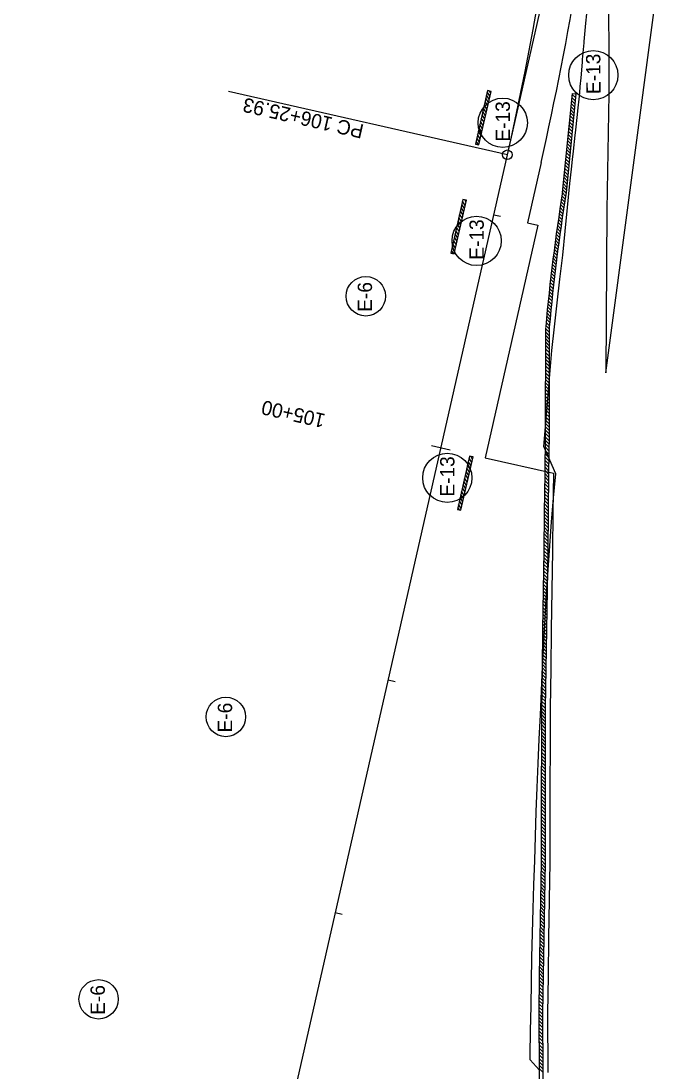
# Model space of a CAD drawing. Extents: x 1710760 to 1713003, y 548603 to 551142.
# Drawn here: x 1712246.8 to 1712516.1, y 550141.7 to 550581.9 of the extents above; entities that cross this region are included whole.
import ezdxf

# ---------------------------------------------------------------- set-up
doc = ezdxf.new("R2010")
doc.units = 0
for name, color, linetype in [('R_Erosion', 7, 'Continuous'), ('R_Erosion_STG 2', 7, 'Continuous'), ('R_Horz Alg', 7, 'Continuous'), ('R_Horz Alg Annot', 7, 'Continuous'), ('R_MOT', 7, 'Continuous'), ('R_No Plot', 7, 'Continuous'), ('R_Proposed Const Limits_Fill', 7, 'Continuous')]:
    doc.layers.add(name, color=color, linetype=linetype)

msp = doc.modelspace()

# ---------------------------------------------------------------- linework, layer by layer
at = {"layer": 'R_Erosion'}
for p, q in [((1712438.87, 550529.97), (1712443.96, 550552.4)), ((1712443.2, 550549.06), (1712442.07, 550550.86)), ((1712443.52, 550550.44), (1712442.39, 550552.23)), ((1712443.83, 550551.82), (1712443.38, 550552.53)), ((1712473.95, 550510.04), (1712478.07, 550551.54)), ((1712479.56, 550551.39), (1712475.44, 550509.9)), ((1712479.4, 550549.75), (1712478.03, 550551.14)), ((1712478.07, 550551.54), (1712479.56, 550551.39)), ((1712479.52, 550551.05), (1712479.14, 550551.43)), ((1712442.26, 550544.92), (1712441.13, 550546.72)), ((1712442.58, 550546.3), (1712441.45, 550548.1)), ((1712442.89, 550547.68), (1712441.76, 550549.48)), ((1712479.01, 550545.88), (1712477.64, 550547.26)), ((1712479.14, 550547.17), (1712477.77, 550548.55)), ((1712479.27, 550548.46), (1712477.9, 550549.85)), ((1712441.32, 550540.79), (1712440.19, 550542.58)), ((1712441.64, 550542.17), (1712440.51, 550543.96)), ((1712441.95, 550543.54), (1712440.82, 550545.34)), ((1712478.5, 550540.71), (1712477.13, 550542.09)), ((1712478.63, 550542), (1712477.26, 550543.38)), ((1712478.75, 550543.29), (1712477.38, 550544.68)), ((1712478.88, 550544.58), (1712477.51, 550545.97)), ((1712440.39, 550536.65), (1712439.25, 550538.44)), ((1712440.7, 550538.03), (1712439.57, 550539.82)), ((1712441.01, 550539.41), (1712439.88, 550541.2)), ((1712478.11, 550536.83), (1712476.74, 550538.21)), ((1712478.24, 550538.12), (1712476.87, 550539.51)), ((1712478.37, 550539.41), (1712477, 550540.8)), ((1712439.13, 550531.13), (1712438, 550532.93)), ((1712439.45, 550532.51), (1712438.32, 550534.31)), ((1712439.76, 550533.89), (1712438.63, 550535.69)), ((1712440.07, 550535.27), (1712438.94, 550537.06)), ((1712477.6, 550531.66), (1712476.23, 550533.04)), ((1712477.73, 550532.95), (1712476.36, 550534.34)), ((1712477.86, 550534.24), (1712476.49, 550535.63)), ((1712477.99, 550535.54), (1712476.62, 550536.92)), ((1712438.65, 550530.02), (1712437.69, 550531.55)), ((1712477.22, 550527.78), (1712475.85, 550529.17)), ((1712477.35, 550529.07), (1712475.98, 550530.46)), ((1712477.47, 550530.37), (1712476.1, 550531.75)), ((1712476.83, 550523.9), (1712475.46, 550525.29)), ((1712476.96, 550525.2), (1712475.59, 550526.58)), ((1712477.09, 550526.49), (1712475.72, 550527.87)), ((1712476.32, 550518.73), (1712474.95, 550520.12)), ((1712476.45, 550520.03), (1712475.08, 550521.41)), ((1712476.58, 550521.32), (1712475.21, 550522.7)), ((1712476.7, 550522.61), (1712475.33, 550524)), ((1712475.94, 550514.86), (1712474.57, 550516.24)), ((1712476.06, 550516.15), (1712474.69, 550517.53)), ((1712476.19, 550517.44), (1712474.82, 550518.83)), ((1712475.41, 550509.7), (1712474.05, 550511.07)), ((1712475.55, 550510.98), (1712474.18, 550512.36)), ((1712475.68, 550512.27), (1712474.31, 550513.66)), ((1712475.81, 550513.56), (1712474.44, 550514.95)), ((1712428.56, 550484.29), (1712433.65, 550506.72)), ((1712433.49, 550505.99), (1712432.92, 550506.89)), ((1712474.82, 550506.03), (1712473.51, 550507.35)), ((1712475.02, 550507.25), (1712473.71, 550508.58)), ((1712475.21, 550508.48), (1712473.91, 550509.8)), ((1712432.23, 550500.47), (1712431.1, 550502.27)), ((1712432.55, 550501.85), (1712431.42, 550503.65)), ((1712432.86, 550503.23), (1712431.73, 550505.03)), ((1712433.17, 550504.61), (1712432.04, 550506.4)), ((1712474.07, 550501.1), (1712472.75, 550502.43)), ((1712474.25, 550502.34), (1712472.94, 550503.67)), ((1712474.44, 550503.57), (1712473.13, 550504.9)), ((1712474.63, 550504.8), (1712473.32, 550506.12)), ((1712431.29, 550496.33), (1712430.16, 550498.13)), ((1712431.61, 550497.71), (1712430.48, 550499.51)), ((1712431.92, 550499.09), (1712430.79, 550500.89)), ((1712473.52, 550497.39), (1712472.2, 550498.73)), ((1712473.7, 550498.63), (1712472.38, 550499.96)), ((1712473.88, 550499.87), (1712472.56, 550501.2)), ((1712430.35, 550492.2), (1712429.22, 550493.99)), ((1712430.67, 550493.58), (1712429.54, 550495.37)), ((1712430.98, 550494.96), (1712429.85, 550496.75)), ((1712472.81, 550492.42), (1712471.48, 550493.76)), ((1712472.98, 550493.66), (1712471.66, 550495)), ((1712473.16, 550494.91), (1712471.84, 550496.25)), ((1712473.34, 550496.15), (1712472.02, 550497.49)), ((1712429.41, 550488.06), (1712428.28, 550489.86)), ((1712429.73, 550489.44), (1712428.6, 550491.23)), ((1712430.04, 550490.82), (1712428.91, 550492.61)), ((1712472.3, 550488.67), (1712470.97, 550490.02)), ((1712472.47, 550489.92), (1712471.14, 550491.27)), ((1712472.64, 550491.17), (1712471.31, 550492.51)), ((1712428.19, 550484.37), (1712427.34, 550485.72)), ((1712428.79, 550485.3), (1712427.66, 550487.1)), ((1712429.1, 550486.68), (1712427.97, 550488.48)), ((1712471.64, 550483.64), (1712470.3, 550485)), ((1712471.8, 550484.9), (1712470.47, 550486.26)), ((1712471.97, 550486.16), (1712470.63, 550487.51)), ((1712472.13, 550487.42), (1712470.8, 550488.76)), ((1712471.17, 550479.86), (1712469.83, 550481.21)), ((1712471.33, 550481.12), (1712469.98, 550482.48)), ((1712471.48, 550482.38), (1712470.14, 550483.74)), ((1712470.57, 550474.78), (1712469.21, 550476.14)), ((1712470.71, 550476.05), (1712469.36, 550477.41)), ((1712470.86, 550477.32), (1712469.52, 550478.68)), ((1712471.02, 550478.59), (1712469.67, 550479.95)), ((1712470.13, 550470.95), (1712468.78, 550472.32)), ((1712470.27, 550472.23), (1712468.92, 550473.6)), ((1712470.42, 550473.5), (1712469.07, 550474.87)), ((1712469.58, 550465.82), (1712468.22, 550467.2)), ((1712469.72, 550467.1), (1712468.35, 550468.48)), ((1712469.85, 550468.39), (1712468.49, 550469.76)), ((1712469.99, 550469.67), (1712468.63, 550471.04)), ((1712469.19, 550461.95), (1712467.82, 550463.33)), ((1712469.32, 550463.24), (1712467.95, 550464.62)), ((1712469.45, 550464.53), (1712468.08, 550465.91)), ((1712468.69, 550456.76), (1712467.32, 550458.15)), ((1712468.81, 550458.06), (1712467.44, 550459.45)), ((1712468.94, 550459.36), (1712467.56, 550460.75)), ((1712469.06, 550460.65), (1712467.69, 550462.04)), ((1712468.39, 550452.8), (1712466.96, 550454.25)), ((1712468.46, 550454.16), (1712467.08, 550455.55)), ((1712468.58, 550455.46), (1712467.2, 550456.85)), ((1712468.39, 550451.38), (1712466.89, 550452.89)), ((1712468.39, 550449.96), (1712466.89, 550451.47)), ((1712468.38, 550448.54), (1712466.89, 550450.06)), ((1712468.38, 550447.12), (1712466.88, 550448.64)), ((1712468.38, 550445.7), (1712466.88, 550447.22)), ((1712468.38, 550444.28), (1712466.88, 550445.8)), ((1712468.37, 550441.45), (1712466.87, 550442.96)), ((1712468.37, 550440.03), (1712466.87, 550441.54)), ((1712468.37, 550442.87), (1712466.88, 550444.38)), ((1712468.36, 550437.19), (1712466.86, 550438.7)), ((1712468.36, 550435.77), (1712466.86, 550437.28)), ((1712468.36, 550438.61), (1712466.87, 550440.12)), ((1712468.35, 550432.93), (1712466.85, 550434.45)), ((1712468.35, 550431.51), (1712466.85, 550433.03)), ((1712468.35, 550434.35), (1712466.86, 550435.86)), ((1712468.34, 550427.26), (1712466.84, 550428.77)), ((1712468.34, 550425.84), (1712466.84, 550427.35)), ((1712468.35, 550430.09), (1712466.85, 550431.61)), ((1712468.34, 550428.67), (1712466.85, 550430.19)), ((1712468.33, 550423), (1712466.83, 550424.51)), ((1712468.33, 550421.58), (1712466.83, 550423.09)), ((1712468.33, 550424.42), (1712466.84, 550425.93)), ((1712468.32, 550418.74), (1712466.82, 550420.25)), ((1712468.32, 550417.32), (1712466.82, 550418.84)), ((1712468.32, 550420.16), (1712466.83, 550421.67)), ((1712468.31, 550413.06), (1712466.81, 550414.58)), ((1712468.32, 550415.9), (1712466.82, 550417.42)), ((1712468.31, 550414.48), (1712466.82, 550416)), ((1712468.3, 550408.81), (1712466.8, 550410.32)), ((1712468.31, 550411.65), (1712466.81, 550413.16)), ((1712468.3, 550410.23), (1712466.81, 550411.74)), ((1712468.26, 550404.59), (1712466.77, 550406.09)), ((1712468.27, 550405.99), (1712466.79, 550407.49)), ((1712468.29, 550407.4), (1712466.8, 550408.9)), ((1712468.21, 550400.37), (1712466.72, 550401.87)), ((1712468.22, 550401.77), (1712466.74, 550403.27)), ((1712468.24, 550403.18), (1712466.76, 550404.68)), ((1712431.32, 550376.76), (1712436.41, 550399.19)), ((1712435.56, 550395.45), (1712434.43, 550397.24)), ((1712435.87, 550396.83), (1712434.74, 550398.62)), ((1712436.19, 550398.21), (1712435.42, 550399.42)), ((1712468.16, 550396.15), (1712466.68, 550397.65)), ((1712468.18, 550397.56), (1712466.69, 550399.06)), ((1712468.19, 550398.96), (1712466.71, 550400.46)), ((1712434.62, 550391.31), (1712433.49, 550393.1)), ((1712434.93, 550392.69), (1712433.8, 550394.48)), ((1712435.25, 550394.07), (1712434.12, 550395.86)), ((1712468.11, 550391.93), (1712466.63, 550393.43)), ((1712468.13, 550393.34), (1712466.64, 550394.84)), ((1712468.14, 550394.74), (1712466.66, 550396.24)), ((1712433.68, 550387.17), (1712432.55, 550388.97)), ((1712433.99, 550388.55), (1712432.86, 550390.35)), ((1712434.31, 550389.93), (1712433.18, 550391.73)), ((1712468.05, 550386.31), (1712466.56, 550387.81)), ((1712468.06, 550387.72), (1712466.58, 550389.21)), ((1712468.08, 550389.12), (1712466.6, 550390.62)), ((1712468.1, 550390.53), (1712466.61, 550392.03)), ((1712432.43, 550381.66), (1712431.3, 550383.45)), ((1712432.74, 550383.04), (1712431.61, 550384.83)), ((1712433.05, 550384.41), (1712431.92, 550386.21)), ((1712433.37, 550385.79), (1712432.24, 550387.59)), ((1712468, 550382.09), (1712466.52, 550383.59)), ((1712468.02, 550383.5), (1712466.53, 550385)), ((1712468.03, 550384.9), (1712466.55, 550386.4)), ((1712431.49, 550377.52), (1712430.36, 550379.31)), ((1712431.8, 550378.9), (1712430.67, 550380.69)), ((1712432.11, 550380.28), (1712430.98, 550382.07)), ((1712467.95, 550377.87), (1712466.47, 550379.37)), ((1712467.97, 550379.28), (1712466.48, 550380.78)), ((1712467.98, 550380.69), (1712466.5, 550382.19)), ((1712430.69, 550376.9), (1712430.04, 550377.93)), ((1712467.9, 550373.66), (1712466.42, 550375.16)), ((1712467.92, 550375.06), (1712466.44, 550376.56)), ((1712467.94, 550376.47), (1712466.45, 550377.97)), ((1712467.86, 550369.44), (1712466.37, 550370.94)), ((1712467.87, 550370.84), (1712466.39, 550372.34)), ((1712467.89, 550372.25), (1712466.4, 550373.75)), ((1712467.81, 550365.22), (1712466.32, 550366.72)), ((1712467.82, 550366.63), (1712466.34, 550368.13)), ((1712467.84, 550368.03), (1712466.36, 550369.53)), ((1712467.76, 550361), (1712466.28, 550362.5)), ((1712467.77, 550362.41), (1712466.29, 550363.91)), ((1712467.79, 550363.81), (1712466.31, 550365.31)), ((1712467.68, 550355.4), (1712466.2, 550356.89)), ((1712467.7, 550356.8), (1712466.22, 550358.29)), ((1712467.72, 550358.2), (1712466.24, 550359.69)), ((1712467.74, 550359.6), (1712466.26, 550361.1)), ((1712467.61, 550351.2), (1712466.14, 550352.69)), ((1712467.63, 550352.6), (1712466.16, 550354.09)), ((1712467.66, 550354), (1712466.18, 550355.49)), ((1712467.55, 550347), (1712466.07, 550348.49)), ((1712467.57, 550348.4), (1712466.09, 550349.89)), ((1712467.59, 550349.8), (1712466.11, 550351.29)), ((1712467.48, 550342.79), (1712466.01, 550344.29)), ((1712467.5, 550344.19), (1712466.03, 550345.69)), ((1712467.53, 550345.6), (1712466.05, 550347.09)), ((1712467.42, 550338.59), (1712465.94, 550340.09)), ((1712467.44, 550339.99), (1712465.96, 550341.49)), ((1712467.46, 550341.39), (1712465.98, 550342.89)), ((1712467.35, 550334.39), (1712465.88, 550335.89)), ((1712467.38, 550335.79), (1712465.9, 550337.29)), ((1712467.4, 550337.19), (1712465.92, 550338.69)), ((1712467.29, 550330.19), (1712465.81, 550331.69)), ((1712467.31, 550331.59), (1712465.83, 550333.09)), ((1712467.33, 550332.99), (1712465.86, 550334.49)), ((1712467.2, 550324.59), (1712465.73, 550326.08)), ((1712467.22, 550325.99), (1712465.75, 550327.48)), ((1712467.25, 550327.39), (1712465.77, 550328.88)), ((1712467.27, 550328.79), (1712465.79, 550330.29)), ((1712467.14, 550320.39), (1712465.66, 550321.88)), ((1712467.16, 550321.79), (1712465.68, 550323.28)), ((1712467.18, 550323.19), (1712465.7, 550324.68)), ((1712467.07, 550316.19), (1712465.6, 550317.68)), ((1712467.1, 550317.59), (1712465.62, 550319.08)), ((1712467.12, 550318.99), (1712465.64, 550320.48)), ((1712467.01, 550311.99), (1712465.53, 550313.48)), ((1712467.03, 550313.39), (1712465.55, 550314.88)), ((1712467.05, 550314.79), (1712465.57, 550316.28)), ((1712466.94, 550307.79), (1712465.47, 550309.28)), ((1712466.97, 550309.19), (1712465.49, 550310.68)), ((1712466.99, 550310.59), (1712465.51, 550312.08)), ((1712466.88, 550303.59), (1712465.4, 550305.08)), ((1712466.9, 550304.99), (1712465.42, 550306.48)), ((1712466.92, 550306.39), (1712465.45, 550307.88)), ((1712466.81, 550299.39), (1712465.34, 550300.88)), ((1712466.84, 550300.79), (1712465.36, 550302.28)), ((1712466.86, 550302.19), (1712465.38, 550303.68)), ((1712466.73, 550293.78), (1712465.25, 550295.28)), ((1712466.75, 550295.18), (1712465.27, 550296.68)), ((1712466.77, 550296.58), (1712465.29, 550298.08)), ((1712466.79, 550297.98), (1712465.32, 550299.48)), ((1712466.72, 550289.53), (1712465.22, 550291.04)), ((1712466.73, 550292.36), (1712465.23, 550293.88)), ((1712466.72, 550290.94), (1712465.23, 550292.46)), ((1712466.72, 550288.11), (1712465.22, 550289.62)), ((1712466.72, 550286.69), (1712465.22, 550288.2)), ((1712466.71, 550285.27), (1712465.22, 550286.78)), ((1712466.71, 550283.85), (1712465.21, 550285.36)), ((1712466.71, 550282.43), (1712465.21, 550283.94)), ((1712466.7, 550281.01), (1712465.21, 550282.52)), ((1712466.7, 550278.17), (1712465.2, 550279.68)), ((1712466.7, 550276.75), (1712465.2, 550278.26)), ((1712466.7, 550279.59), (1712465.21, 550281.1)), ((1712466.69, 550273.91), (1712465.19, 550275.43)), ((1712466.69, 550272.49), (1712465.19, 550274.01)), ((1712466.69, 550275.33), (1712465.2, 550276.84)), ((1712466.68, 550268.23), (1712465.18, 550269.75)), ((1712466.69, 550271.07), (1712465.19, 550272.59)), ((1712466.68, 550269.65), (1712465.19, 550271.17)), ((1712466.68, 550266.81), (1712465.18, 550268.33)), ((1712466.68, 550265.4), (1712465.18, 550266.91)), ((1712466.67, 550263.98), (1712465.18, 550265.49)), ((1712466.67, 550262.56), (1712465.17, 550264.07)), ((1712466.67, 550261.14), (1712465.17, 550262.65)), ((1712466.66, 550259.72), (1712465.17, 550261.23)), ((1712466.66, 550258.3), (1712465.16, 550259.81)), ((1712466.66, 550256.88), (1712465.16, 550258.39)), ((1712466.66, 550255.46), (1712465.16, 550256.97)), ((1712466.65, 550252.62), (1712465.15, 550254.13)), ((1712466.65, 550251.2), (1712465.15, 550252.72)), ((1712466.65, 550249.78), (1712465.15, 550251.3)), ((1712466.65, 550254.04), (1712465.16, 550255.55)), ((1712466.64, 550246.94), (1712465.14, 550248.46)), ((1712466.64, 550245.52), (1712465.14, 550247.04)), ((1712466.64, 550248.36), (1712465.15, 550249.88)), ((1712466.63, 550241.27), (1712465.13, 550242.78)), ((1712466.64, 550244.1), (1712465.14, 550245.62)), ((1712466.63, 550242.69), (1712465.14, 550244.2)), ((1712466.62, 550237.01), (1712465.12, 550238.52)), ((1712466.63, 550239.85), (1712465.13, 550241.36)), ((1712466.62, 550238.43), (1712465.13, 550239.94)), ((1712466.62, 550235.59), (1712465.12, 550237.1)), ((1712466.62, 550234.17), (1712465.12, 550235.68)), ((1712466.61, 550232.75), (1712465.12, 550234.26)), ((1712466.61, 550231.33), (1712465.11, 550232.84)), ((1712466.61, 550229.91), (1712465.11, 550231.42)), ((1712466.59, 550228.5), (1712465.11, 550230)), ((1712466.53, 550224.3), (1712465.05, 550225.8)), ((1712466.55, 550225.7), (1712465.07, 550227.2)), ((1712466.57, 550227.1), (1712465.1, 550228.6)), ((1712466.46, 550220.1), (1712464.99, 550221.6)), ((1712466.48, 550221.5), (1712465.01, 550223)), ((1712466.51, 550222.9), (1712465.03, 550224.4)), ((1712466.37, 550214.5), (1712464.9, 550216)), ((1712466.4, 550215.9), (1712464.92, 550217.4)), ((1712466.42, 550217.3), (1712464.94, 550218.8)), ((1712466.44, 550218.7), (1712464.96, 550220.2)), ((1712466.31, 550210.3), (1712464.83, 550211.8)), ((1712466.33, 550211.7), (1712464.85, 550213.2)), ((1712466.35, 550213.1), (1712464.88, 550214.6)), ((1712466.24, 550206.1), (1712464.77, 550207.6)), ((1712466.27, 550207.5), (1712464.79, 550209)), ((1712466.29, 550208.9), (1712464.81, 550210.4)), ((1712466.18, 550201.9), (1712464.7, 550203.4)), ((1712466.2, 550203.3), (1712464.72, 550204.8)), ((1712466.22, 550204.7), (1712464.74, 550206.2)), ((1712466.11, 550197.7), (1712464.64, 550199.2)), ((1712466.13, 550199.1), (1712464.66, 550200.6)), ((1712466.16, 550200.5), (1712464.68, 550202)), ((1712466.05, 550193.5), (1712464.57, 550195)), ((1712466.07, 550194.9), (1712464.59, 550196.4)), ((1712466.09, 550196.3), (1712464.61, 550197.8)), ((1712465.98, 550189.3), (1712464.5, 550190.8)), ((1712466, 550190.7), (1712464.53, 550192.2)), ((1712466.02, 550192.1), (1712464.55, 550193.6)), ((1712465.89, 550183.7), (1712464.42, 550185.2)), ((1712465.91, 550185.1), (1712464.44, 550186.6)), ((1712465.94, 550186.5), (1712464.46, 550188)), ((1712465.96, 550187.9), (1712464.48, 550189.4)), ((1712465.83, 550179.5), (1712464.35, 550181)), ((1712465.85, 550180.9), (1712464.37, 550182.4)), ((1712465.87, 550182.3), (1712464.39, 550183.8)), ((1712465.76, 550175.31), (1712464.28, 550176.8)), ((1712465.78, 550176.7), (1712464.31, 550178.2)), ((1712465.8, 550178.1), (1712464.33, 550179.6)), ((1712465.7, 550171.11), (1712464.22, 550172.6)), ((1712465.72, 550172.51), (1712464.24, 550174)), ((1712465.74, 550173.91), (1712464.26, 550175.4)), ((1712465.63, 550166.91), (1712464.15, 550168.4)), ((1712465.65, 550168.31), (1712464.17, 550169.8)), ((1712465.67, 550169.71), (1712464.2, 550171.2)), ((1712465.62, 550164.07), (1712464.11, 550165.59)), ((1712465.63, 550162.64), (1712464.12, 550164.17)), ((1712465.61, 550165.5), (1712464.13, 550167)), ((1712465.63, 550161.21), (1712464.13, 550162.74)), ((1712465.64, 550159.78), (1712464.13, 550161.31)), ((1712465.65, 550158.36), (1712464.14, 550159.88)), ((1712465.65, 550156.93), (1712464.15, 550158.45)), ((1712465.66, 550155.5), (1712464.15, 550157.02)), ((1712465.67, 550154.07), (1712464.16, 550155.59)), ((1712465.67, 550152.64), (1712464.17, 550154.16)), ((1712465.68, 550151.21), (1712464.17, 550152.74)), ((1712465.69, 550149.78), (1712464.18, 550151.31)), ((1712465.69, 550148.35), (1712464.19, 550149.88)), ((1712465.7, 550146.92), (1712464.19, 550148.45)), ((1712465.71, 550145.5), (1712464.2, 550147.02)), ((1712465.71, 550144.07), (1712464.21, 550145.59)), ((1712465.72, 550142.64), (1712464.21, 550144.16)), ((1712465.73, 550141.21), (1712464.22, 550142.73))]:
    msp.add_line(p, q, dxfattribs=at)
for points in [[(1712443.96, 550552.4), (1712442.5, 550552.73), (1712437.41, 550530.3), (1712438.87, 550529.97)], [(1712433.65, 550506.72), (1712432.19, 550507.05), (1712427.1, 550484.62), (1712428.56, 550484.29)], [(1712464.29, 550127.23), (1712464.23, 550141.11), (1712464.11, 550165.8), (1712464.36, 550181.72), (1712464.61, 550197.61), (1712464.86, 550213.49), (1712465.11, 550229.35), (1712465.14, 550245.45), (1712465.17, 550261.57), (1712465.2, 550277.69), (1712465.23, 550293.84), (1712465.48, 550310.36), (1712465.74, 550326.86), (1712465.99, 550343.35), (1712466.25, 550359.84), (1712466.43, 550376.03), (1712466.62, 550392.23), (1712466.8, 550408.42), (1712466.89, 550453.35)], [(1712468.39, 550453.34), (1712468.3, 550408.41), (1712468.11, 550392.22), (1712467.93, 550376.02), (1712467.75, 550359.82), (1712467.49, 550343.33), (1712467.24, 550326.83), (1712466.98, 550310.34), (1712466.73, 550293.83), (1712466.7, 550277.69), (1712466.67, 550261.57), (1712466.64, 550245.44), (1712466.61, 550229.34), (1712466.36, 550213.47), (1712466.11, 550197.58), (1712465.86, 550181.7), (1712465.61, 550165.8), (1712465.73, 550141.11), (1712465.79, 550127.24)], [(1712436.41, 550399.19), (1712434.95, 550399.52), (1712429.85, 550377.1), (1712431.32, 550376.76)]]:
    msp.add_lwpolyline(points, dxfattribs=at)
for centre in [(1712391.42, 550466.48), (1712332.73, 550290.14), (1712279.35, 550171.78)]:
    msp.add_circle(centre, 8.26, dxfattribs=at)
for radius in [779.28, 777.78]:
    msp.add_arc((1713243.2, 550385.42), radius, 170.78152, 174.9772, dxfattribs=at)
at = {"layer": 'R_Erosion_STG 2'}
for centre in [(1712486.86, 550559.16), (1712448.87, 550539.22), (1712437.91, 550489.71), (1712425.61, 550390.38)]:
    msp.add_circle(centre, 10.32, dxfattribs=at)
at = {"layer": 'R_Horz Alg'}
msp.add_line((1712246.77, 549627.28), (1712450.81, 550525.82), dxfattribs=at)
msp.add_arc((1711136.14, 550824.35), 1348.14, 347.20664, 359.34976, dxfattribs=at)
at = {"layer": 'R_Horz Alg Annot'}
msp.add_line((1712450.81, 550525.82), (1712482.56, 550665.66), dxfattribs=at)
for points in [[(1712450.81, 550525.82), (1712333.79, 550552.4)], [(1712447.99, 550499.87), (1712445.07, 550500.54)], [(1712419.02, 550403.91), (1712426.82, 550402.14)], [(1712403.7, 550304.84), (1712400.78, 550305.5)], [(1712381.56, 550207.32), (1712378.64, 550207.99)]]:
    msp.add_lwpolyline(points, dxfattribs=at)
msp.add_circle((1712450.81, 550525.82), 2, dxfattribs=at)
at = {"layer": 'R_MOT'}
msp.add_line((1712492.09, 550434.45), (1712516.1, 550614.45), dxfattribs=at)
msp.add_lwpolyline([(1712493.23, 550586.21), (1712493.31, 550568.79), (1712493.38, 550551.37), (1712493.12, 550535.16), (1712492.85, 550518.96), (1712492.58, 550502.75), (1712492.09, 550434.45)], dxfattribs=at)
at = {"layer": 'R_No Plot'}
for p, q in [((1712464.95, 550522.61), (1712459.21, 550497.33)), ((1712463.59, 550496.33), (1712441.45, 550398.81)), ((1712459.21, 550497.33), (1712463.59, 550496.33)), ((1712441.45, 550398.81), (1712470.12, 550392.31))]:
    msp.add_line(p, q, dxfattribs=at)
msp.add_lwpolyline([(1712470.12, 550392.31), (1712470.11, 550392.19), (1712469.93, 550375.99), (1712469.75, 550359.79), (1712469.49, 550343.3), (1712469.24, 550326.8), (1712468.98, 550310.3), (1712468.73, 550293.81), (1712468.7, 550277.69), (1712468.67, 550261.56), (1712468.64, 550245.44), (1712468.61, 550229.32), (1712468.36, 550213.43), (1712468.11, 550197.55), (1712467.86, 550181.67), (1712467.61, 550165.79), (1712467.73, 550141.12)], dxfattribs=at)
msp.add_arc((1711136.14, 550824.35), 1362.64, 347.20664, 354.06382, dxfattribs=at)
at = {"layer": 'R_Proposed Const Limits_Fill'}
msp.add_lwpolyline([(1712464.1, 550142.15), (1712460.38, 550146.47), (1712460.38, 550146.47), (1712460.41, 550148.4), (1712460.57, 550158.62), (1712460.73, 550168.84), (1712460.92, 550179.05), (1712461.14, 550189.25), (1712461.39, 550199.45), (1712461.66, 550209.64), (1712461.97, 550219.83), (1712462.31, 550230.01), (1712462.61, 550240.19), (1712462.96, 550250.37), (1712463.33, 550260.54), (1712463.74, 550270.7), (1712464.18, 550280.85), (1712464.65, 550291), (1712465.12, 550301.15), (1712465.58, 550311.3), (1712466.1, 550321.43), (1712466.64, 550331.57), (1712467.24, 550341.69), (1712467.94, 550351.78), (1712468.59, 550361.89), (1712469.33, 550371.97), (1712470.14, 550382.05), (1712471.13, 550392.07), (1712466.04, 550403.49), (1712466.91, 550413.54), (1712467.82, 550423.59), (1712468.69, 550433.65), (1712469.52, 550443.71), (1712470.54, 550453.74), (1712471.68, 550463.73), (1712472.84, 550473.72), (1712474.05, 550483.7), (1712475.04, 550493.73), (1712476.05, 550503.76), (1712477.08, 550513.78), (1712477.73, 550519.71), (1712478.17, 550523.87), (1712478.56, 550527.39), (1712479.29, 550534.06), (1712479.4, 550535.05), (1712480.21, 550542.71), (1712480.37, 550544.25), (1712481.02, 550550.36), (1712481.16, 550551.79), (1712481.4, 550554.43), (1712481.71, 550558.03), (1712482.26, 550564.63), (1712482.35, 550565.69), (1712482.97, 550572.67), (1712483.04, 550573.34), (1712483.18, 550574.8), (1712483.77, 550580.98), (1712484.15, 550584.95)], dxfattribs=at)

# ---------------------------------------------------------------- texts
at = {"layer": 'R_Erosion'}
for p in [(1712394.03, 550459.98), (1712335.34, 550283.64), (1712281.95, 550165.28)]:
    msp.add_text('E-6 ', height=5.999, rotation=90, dxfattribs=at).set_placement(p)
at = {"layer": 'R_Erosion_STG 2'}
for rotation, p in [(90.4005, (1712489.92, 550551.26)), (90, (1712451.87, 550531.31)), (90, (1712440.91, 550481.8)), (90, (1712428.61, 550382.47))]:
    msp.add_text('E-13', height=5.999, rotation=rotation, dxfattribs=at).set_placement(p)
at = {"layer": 'R_Horz Alg Annot'}
for s, p in [('PC 106+25.93', (1712390.97, 550538.39)), ('105+00', (1712374.83, 550417.02))]:
    msp.add_text(s, height=6, rotation=167.2066, dxfattribs=at).set_placement(p)

doc.saveas('drawing.dxf')
